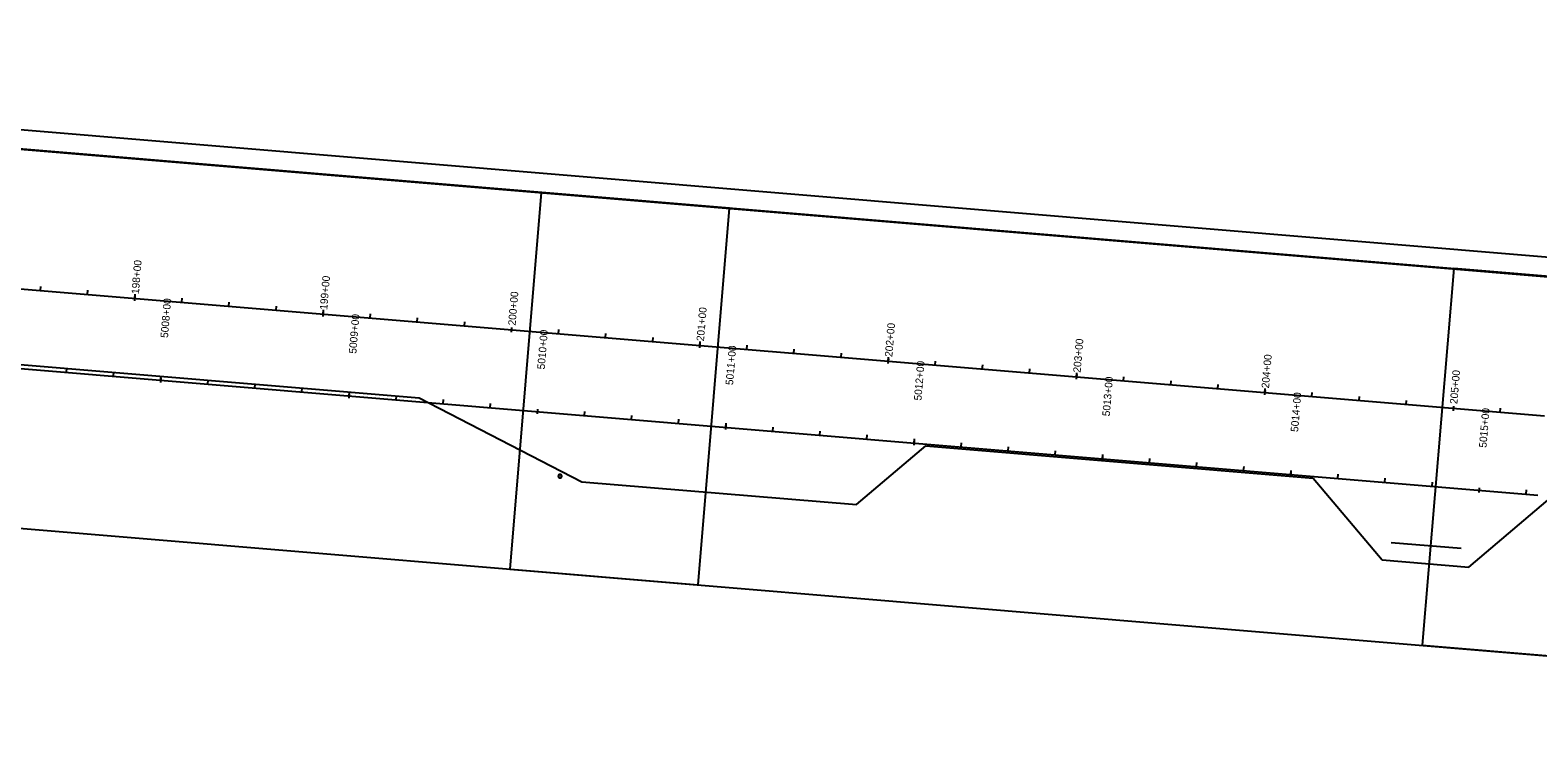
# Model space of a CAD drawing. Extents: x 20500393 to 20505339, y 7953466 to 7954298.
# Drawn here: x 20503447 to 20504244, y 7953510 to 7953887 of the extents above; entities that cross this region are included whole.
import ezdxf

# ---------------------------------------------------------------- set-up
doc = ezdxf.new("R2010")
doc.units = 0
for name, color, linetype in [('_CIVIL_CONSTRUCTION', 7, 'Continuous'), ('Alignment', 7, 'Continuous'), ('Draft_2', 7, 'Continuous'), ('Draft_3', 7, 'Continuous'), ('Draft_7', 7, 'Continuous'), ('NamedBoundary', 7, 'Continuous'), ('RowProposed', 7, 'Continuous'), ('TextAlignmentLrg', 7, 'Continuous'), ('TextAlignmentSml', 7, 'Continuous')]:
    doc.layers.add(name, color=color, linetype=linetype)

msp = doc.modelspace()

# ---------------------------------------------------------------- linework, layer by layer
at = {"layer": '_CIVIL_CONSTRUCTION'}
for p, q in [((20502804.53, 7953803.04), (20504247.96, 7953682.58)), ((20502804.53, 7953803.04), (20504247.96, 7953682.58)), ((20503303.67, 7953719.24), (20504244.47, 7953640.72))]:
    msp.add_line(p, q, dxfattribs=at)
at = {"layer": 'Alignment'}
msp.add_line((20503303.67, 7953719.24), (20504244.47, 7953640.72), dxfattribs=at)
msp.add_line((20503303.67, 7953719.24), (20504244.47, 7953640.72), dxfattribs=at)
at = {"layer": 'Draft_2'}
for p, q in [((20502811.52, 7953886.75), (20504254.94, 7953766.29)), ((20502810.65, 7953876.37), (20504254.08, 7953755.91)), ((20504203.96, 7953612.4), (20504166.94, 7953615.49))]:
    msp.add_line(p, q, dxfattribs=at)
at = {"layer": 'Draft_3'}
msp.add_line((20503303.67, 7953719.24), (20504244.47, 7953640.72), dxfattribs=at)
msp.add_line((20503303.67, 7953719.24), (20504244.47, 7953640.72), dxfattribs=at)
at = {"layer": 'Draft_7'}
for p, q in [((20503309.44, 7953720.76), (20503652.67, 7953692.12)), ((20503652.67, 7953692.12), (20503738.61, 7953647.82)), ((20503883.91, 7953635.69), (20503920.62, 7953666.75)), ((20503920.62, 7953666.75), (20504125.53, 7953649.65)), ((20503738.61, 7953647.82), (20503883.91, 7953635.69)), ((20504125.53, 7953649.65), (20504162.07, 7953606.46)), ((20504207.89, 7953602.63), (20504252.16, 7953640.08)), ((20504162.07, 7953606.46), (20504207.89, 7953602.63))]:
    msp.add_line(p, q, dxfattribs=at)
at = {"layer": 'NamedBoundary'}
for points in [[(20503199.83, 7953844), (20503183.2, 7953644.69), (20503800.15, 7953593.21), (20503816.78, 7953792.52)], [(20503717.13, 7953800.83), (20503700.49, 7953601.52), (20504282.98, 7953552.91), (20504299.61, 7953752.22)], [(20504199.95, 7953760.54), (20504183.32, 7953561.23), (20504801.82, 7953509.62), (20504818.46, 7953708.92)]]:
    msp.add_lwpolyline(points, close=True, dxfattribs=at)
at = {"layer": 'RowProposed'}
msp.add_lwpolyline([(20503726.59, 7953649.9), (20503727.6, 7953649.9), (20503728.11, 7953650.78), (20503727.6, 7953651.66), (20503726.59, 7953651.66), (20503726.08, 7953650.78)], close=True, dxfattribs=at)
at = {"layer": 'TextAlignmentLrg'}
for p, q in [((20503502.11, 7953744.82), (20503502.29, 7953747)), ((20503601.76, 7953736.51), (20503601.94, 7953738.68)), ((20503701.51, 7953729.41), (20503701.31, 7953726.97)), ((20503801.07, 7953719.87), (20503801.25, 7953722.05)), ((20503900.72, 7953711.56), (20503900.9, 7953713.73)), ((20503515.81, 7953701.53), (20503516, 7953703.71)), ((20504000.37, 7953703.24), (20504000.56, 7953705.42)), ((20503615.47, 7953693.22), (20503615.65, 7953695.39)), ((20504100.03, 7953694.92), (20504100.21, 7953697.1)), ((20504199.78, 7953687.83), (20504199.58, 7953685.39)), ((20503715.22, 7953686.12), (20503715.02, 7953683.68)), ((20503814.78, 7953676.58), (20503814.96, 7953678.76)), ((20503914.43, 7953668.27), (20503914.61, 7953670.44)), ((20504014.08, 7953659.95), (20504014.26, 7953662.13)), ((20504113.74, 7953651.63), (20504113.92, 7953653.81)), ((20504213.49, 7953644.54), (20504213.29, 7953642.1))]:
    msp.add_line(p, q, dxfattribs=at)
at = {"layer": 'TextAlignmentSml'}
for p, q in [((20503452.28, 7953748.98), (20503452.46, 7953751.16)), ((20503477.19, 7953746.9), (20503477.37, 7953749.08)), ((20503502.21, 7953746.04), (20503502, 7953743.6)), ((20503527.02, 7953742.74), (20503527.2, 7953744.92)), ((20503551.93, 7953740.66), (20503552.11, 7953742.84)), ((20503576.85, 7953738.59), (20503577.03, 7953740.76)), ((20503601.86, 7953737.73), (20503601.66, 7953735.29)), ((20503626.67, 7953734.43), (20503626.85, 7953736.6)), ((20503651.59, 7953732.35), (20503651.77, 7953734.52)), ((20503676.5, 7953730.27), (20503676.68, 7953732.45)), ((20503701.51, 7953729.41), (20503701.31, 7953726.97)), ((20503726.33, 7953726.11), (20503726.51, 7953728.29)), ((20503751.24, 7953724.03), (20503751.42, 7953726.21)), ((20503776.15, 7953721.95), (20503776.33, 7953724.13)), ((20503801.17, 7953721.09), (20503800.96, 7953718.65)), ((20503825.98, 7953717.79), (20503826.16, 7953719.97)), ((20503850.89, 7953715.72), (20503851.08, 7953717.89)), ((20503875.81, 7953713.64), (20503875.99, 7953715.81)), ((20503900.82, 7953712.78), (20503900.62, 7953710.34)), ((20503925.63, 7953709.48), (20503925.82, 7953711.65)), ((20503465.99, 7953705.69), (20503466.17, 7953707.87)), ((20503490.9, 7953703.61), (20503491.08, 7953705.79)), ((20503515.92, 7953702.75), (20503515.71, 7953700.31)), ((20503950.55, 7953707.4), (20503950.73, 7953709.58)), ((20503975.46, 7953705.32), (20503975.64, 7953707.5)), ((20504000.48, 7953704.46), (20504000.27, 7953702.02)), ((20504025.29, 7953701.16), (20504025.47, 7953703.34)), ((20503540.73, 7953699.45), (20503540.91, 7953701.63)), ((20503565.64, 7953697.37), (20503565.82, 7953699.55)), ((20503590.55, 7953695.3), (20503590.74, 7953697.47)), ((20504050.2, 7953699.08), (20504050.38, 7953701.26)), ((20504075.11, 7953697), (20504075.3, 7953699.18)), ((20504100.13, 7953696.14), (20504099.93, 7953693.7)), ((20504124.94, 7953692.85), (20504125.12, 7953695.02)), ((20503615.57, 7953694.44), (20503615.37, 7953692)), ((20503640.38, 7953691.14), (20503640.56, 7953693.31)), ((20503665.3, 7953689.06), (20503665.48, 7953691.23)), ((20503690.21, 7953686.98), (20503690.39, 7953689.16)), ((20504149.85, 7953690.77), (20504150.04, 7953692.94)), ((20504174.77, 7953688.69), (20504174.95, 7953690.86)), ((20504199.78, 7953687.83), (20504199.58, 7953685.39)), ((20504224.59, 7953684.53), (20504224.78, 7953686.71)), ((20503715.22, 7953686.12), (20503715.02, 7953683.68)), ((20503740.04, 7953682.82), (20503740.22, 7953685)), ((20503764.95, 7953680.74), (20503765.13, 7953682.92)), ((20503789.86, 7953678.66), (20503790.04, 7953680.84)), ((20503814.88, 7953677.8), (20503814.67, 7953675.36)), ((20503839.69, 7953674.5), (20503839.87, 7953676.68)), ((20503864.6, 7953672.43), (20503864.78, 7953674.6)), ((20503889.52, 7953670.35), (20503889.7, 7953672.52)), ((20503914.53, 7953669.49), (20503914.33, 7953667.05)), ((20503939.34, 7953666.19), (20503939.52, 7953668.36)), ((20503964.26, 7953664.11), (20503964.44, 7953666.29)), ((20503989.17, 7953662.03), (20503989.35, 7953664.21)), ((20504014.18, 7953661.17), (20504013.98, 7953658.73)), ((20504039, 7953657.87), (20504039.18, 7953660.05)), ((20504063.91, 7953655.79), (20504064.09, 7953657.97)), ((20504088.82, 7953653.71), (20504089, 7953655.89)), ((20504113.84, 7953652.85), (20504113.63, 7953650.41)), ((20504138.65, 7953649.56), (20504138.83, 7953651.73)), ((20504163.56, 7953647.48), (20504163.74, 7953649.65)), ((20504188.48, 7953645.4), (20504188.66, 7953647.57)), ((20504213.49, 7953644.54), (20504213.29, 7953642.1)), ((20504238.3, 7953641.24), (20504238.48, 7953643.42))]:
    msp.add_line(p, q, dxfattribs=at)

# ---------------------------------------------------------------- texts
for s, p in [('198+00', (20503504.3, 7953746.97)), ('199+00', (20503603.95, 7953738.65)), ('5008+00', (20503519.68, 7953723.75)), ('200+00', (20503703.6, 7953730.33)), ('5009+00', (20503619.33, 7953715.43)), ('201+00', (20503803.26, 7953722.02)), ('5010+00', (20503718.99, 7953707.12)), ('202+00', (20503902.91, 7953713.7)), ('5011+00', (20503818.64, 7953698.8)), ('203+00', (20504002.56, 7953705.38)), ('5012+00', (20503918.31, 7953690.63)), ('204+00', (20504102.22, 7953697.07)), ('5013+00', (20504017.96, 7953682.31)), ('205+00', (20504201.87, 7953688.75)), ('5014+00', (20504117.61, 7953674)), ('5015+00', (20504217.27, 7953665.68))]:
    msp.add_text(s, height=4.008, rotation=85.22957, dxfattribs=at).set_placement(p)

doc.saveas('drawing.dxf')
